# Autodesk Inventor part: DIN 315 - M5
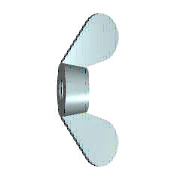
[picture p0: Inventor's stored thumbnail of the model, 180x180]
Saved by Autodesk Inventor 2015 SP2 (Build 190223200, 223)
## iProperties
Created: 2014-02
Part Number: DIN 315 - M5
Material: Stahl, weich
Description: Flügelmutter
Document SubType Name: Modeling
Standard: DIN 315
Designer: rYan
Standard Revision: 1998
Standards Organization: DIN
Language: de-DE
Size Designation: M5
Categories: <MemberInstance><Categories><Category DisplayName="Verbindungselemente" InternalName="e4da775c-781d-43d5-af7c-5136215cf5a6" Mnemonic="FSTN"><Category DisplayNam
Density: 7.85 g/cm^3
Appearance: Halbpoliert
IsCustomPart: 0
Author: rYan
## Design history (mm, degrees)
body "Solid1"
sketch "Skizze1"
  geometry: L1 (0, 0)-(6.5, 0); L2 (0, 0)-(0, 5.5); L3 (6.5, 4.5)-(6.5, 0); L4 (0, 5.5)-(6.136, 11.793); L5 (6.5, 4.5)-(9.692, 5.06); L6 (6.5, 4.5)-(0, 5.5); L7 (6.5, 4.5)-(0, 3.359); A1 r 4 centre (9, 9) between (9.692, 5.06) and (6.136, 11.793)
  constraints: 15 end point, 2 perpendicular, 2 point on circle, 2 tangent, 1 centre point, 1 collinear, 1 horizontal, 1 point on line
  dimensions: "d0" = 9 diameter of L3.start L1 (= KOD2); "d1" = 9 distance from line of L2 A1.centre (= KOH1 - RR); "d2" = 9 vertical distance of L1.end A1.centre (= 0.5 x E0 - RR); "d3" = 4 radius of A1 (= RR); "d4" = 6.5 distance between parallel lines of L2 L3 (= KOH); "d5" = 11 diameter of L2.end L1 (= KOD)
revolve "Körper" stored, may be unused: angle "d57" = 90 deg
extrude "Flügel1" join sketch "Skizze1" stored distance "d6" = 2.3 (= SW); taper "d7" = 0 deg
fillet "Rundung1" dims "d8" = 0.76667 (= 0.333333 x SW)
mirror "Flügel2"
sketch "Skizze2"
  geometry: L1 (0, -14)-(0, 14) reference; L2 (-14, 0)-(14, 0) reference; 1 further point
  constraints: 2 midpoint
hole "Gewinde" sketch "Skizze2" diameter "d97" = 4.134; stored, may be unused: countersink angle "d101" = 82 deg, drill point angle "d103" = 118 deg; dims "d98" = 6, "d99" = 4, "d100" = 2, "d102" = 8
chamfer "Fase1" distance "d9" = 0.43301 (= -0.5 x GD1 + 0.5 x NND); stored, may be unused: angle "d10" = 30 deg, second distance "d109" = 0.43301 (= -0.5 x GD1 + 0.5 x NND)
workaxis "Work Axis1"
workplane "Work Plane1"
other parameters: "NND" = 5 [user parameter; used in 2 equation terms], "KOH" = 6.5 [user parameter; used in 1 equation term], "KOH1" = 13 [user parameter; used in 1 equation term], "SW" = 2.3 [user parameter; used in 2 equation terms], "KOD" = 11 [user parameter; used in 1 equation term], "KOD2" = 9 [user parameter; used in 1 equation term], "RR" = 4 [user parameter; used in 3 equation terms], "E0" = 26 [user parameter; used in 1 equation term], "GD1" = 4.13397 (computed from THREADDIA, PTC, TOA) [user parameter; used in 2 equation terms], "d11" = 0, "d108" = 0, "d110" = 0, "d111" = 0, "d112" = 0, "GUL" = 0.43301 (= 0.541266 x PTC) [user parameter], "BOR" = 0 [user parameter], "PTC" = 0.8 [user parameter; used in 4 equation terms], "THREADDIA" = 5 [user parameter; used in 1 equation term], "TOA" = 30 deg [user parameter; used in 1 equation term], "TPU" = 12.5 (computed from PTC) [user parameter], "RR2" = 2.5 [user parameter], "SW1" = 2.8 [user parameter], "GAL" = 0.43301 (= 0.541266 x PTC) [user parameter]
